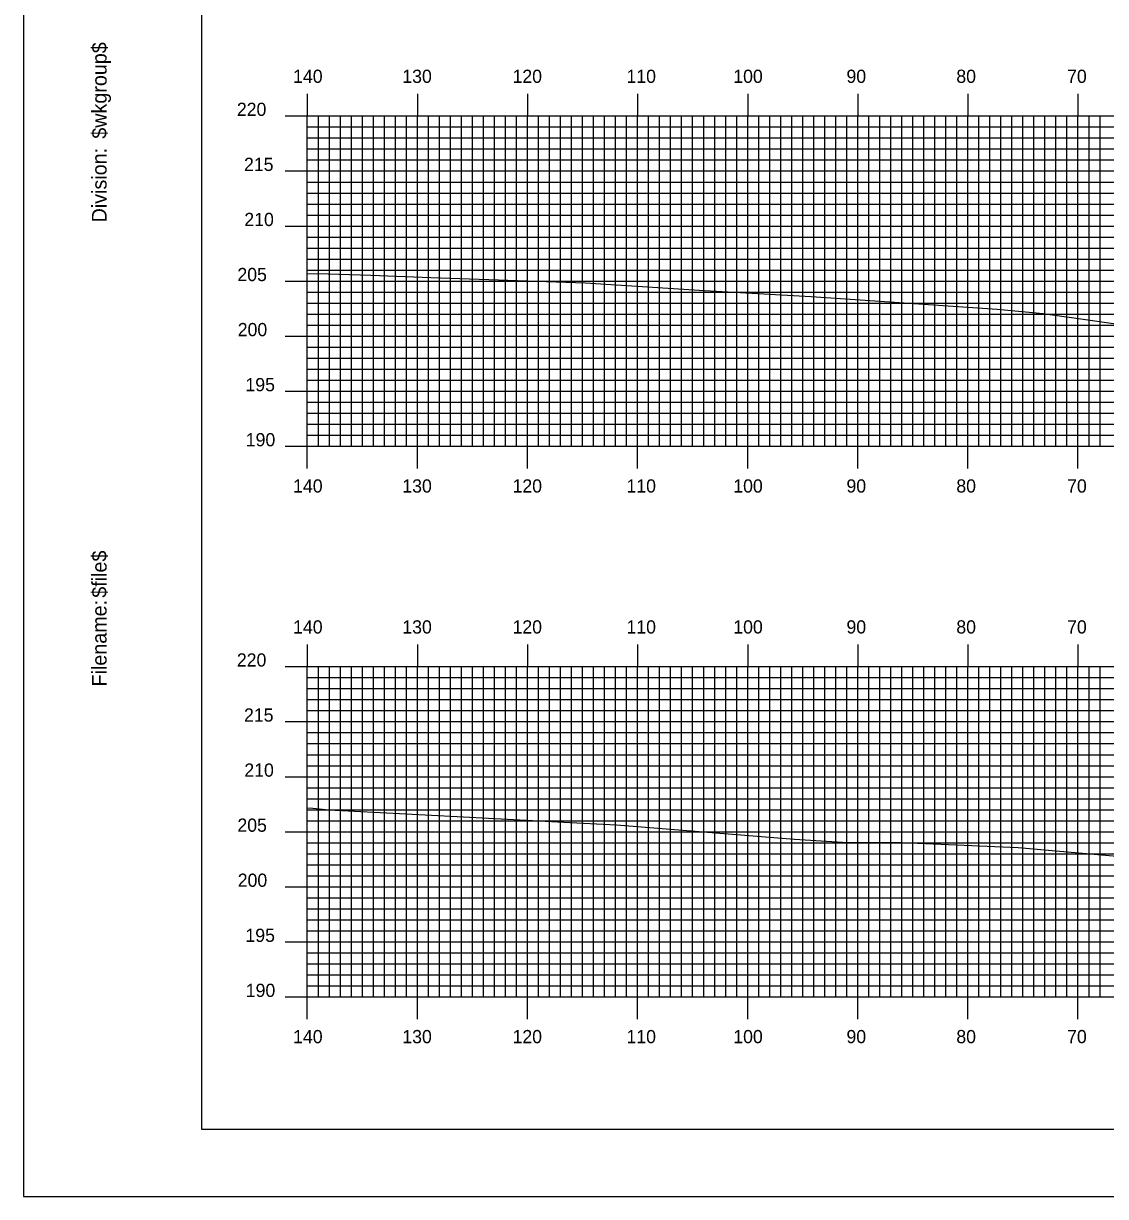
# Model space of a CAD drawing. Extents: x 1806258 to 1806601, y 442591 to 442811.
# Drawn here: x 1806257.9 to 1806356.2, y 442590.5 to 442697.1 of the extents above; entities that cross this region are included whole.
import ezdxf

# ---------------------------------------------------------------- set-up
doc = ezdxf.new("R2010")
doc.units = 0
for name, color, linetype in [('BORDER', 7, 'Continuous'), ('H_V ANNOTATION', 7, 'Continuous'), ('MAJOR', 7, 'Continuous'), ('MINOR', 7, 'Continuous'), ('PLOT BOUNDARY', 7, 'Continuous'), ('S_Roadway_Centerline', 7, 'Continuous')]:
    doc.layers.add(name, color=color, linetype=linetype)

msp = doc.modelspace()

# ---------------------------------------------------------------- linework, layer by layer
at = {"layer": 'BORDER'}
msp.add_lwpolyline([(1806274.13, 442596.67), (1806594.13, 442596.67), (1806594.13, 442806.67), (1806274.13, 442806.67)], close=True, dxfattribs=at)
at = {"layer": 'MAJOR'}
for p, q in [((1806283.73, 442690.67), (1806283.73, 442688.67)), ((1806293.73, 442690.67), (1806293.73, 442688.67)), ((1806303.73, 442690.67), (1806303.73, 442688.67)), ((1806313.73, 442690.67), (1806313.73, 442688.67)), ((1806323.73, 442690.67), (1806323.73, 442688.67)), ((1806333.73, 442690.67), (1806333.73, 442688.67)), ((1806343.73, 442690.67), (1806343.73, 442688.67)), ((1806353.73, 442690.67), (1806353.73, 442688.67)), ((1806281.73, 442688.67), (1806283.73, 442688.67)), ((1806283.73, 442688.67), (1806563.73, 442688.67)), ((1806283.73, 442658.67), (1806283.73, 442688.67)), ((1806283.73, 442658.67), (1806283.73, 442688.67)), ((1806283.73, 442688.67), (1806563.73, 442688.67)), ((1806293.73, 442658.67), (1806293.73, 442688.67)), ((1806303.73, 442658.67), (1806303.73, 442688.67)), ((1806313.73, 442658.67), (1806313.73, 442688.67)), ((1806323.73, 442658.67), (1806323.73, 442688.67)), ((1806333.73, 442658.67), (1806333.73, 442688.67)), ((1806343.73, 442658.67), (1806343.73, 442688.67)), ((1806353.73, 442658.67), (1806353.73, 442688.67)), ((1806281.73, 442683.67), (1806283.73, 442683.67)), ((1806283.73, 442683.67), (1806563.73, 442683.67)), ((1806281.73, 442678.67), (1806283.73, 442678.67)), ((1806283.73, 442678.67), (1806563.73, 442678.67)), ((1806281.73, 442673.67), (1806283.73, 442673.67)), ((1806283.73, 442673.67), (1806563.73, 442673.67)), ((1806281.73, 442668.67), (1806283.73, 442668.67)), ((1806283.73, 442668.67), (1806563.73, 442668.67)), ((1806281.73, 442663.67), (1806283.73, 442663.67)), ((1806283.73, 442663.67), (1806563.73, 442663.67)), ((1806281.73, 442658.67), (1806283.73, 442658.67)), ((1806283.73, 442658.67), (1806563.73, 442658.67)), ((1806283.73, 442658.67), (1806563.73, 442658.67)), ((1806283.73, 442656.66), (1806283.73, 442658.67)), ((1806293.73, 442656.66), (1806293.73, 442658.67)), ((1806303.73, 442656.66), (1806303.73, 442658.67)), ((1806313.73, 442656.66), (1806313.73, 442658.67)), ((1806323.73, 442656.66), (1806323.73, 442658.67)), ((1806333.73, 442656.66), (1806333.73, 442658.67)), ((1806343.73, 442656.66), (1806343.73, 442658.67)), ((1806353.73, 442656.66), (1806353.73, 442658.67)), ((1806283.73, 442640.67), (1806283.73, 442638.67)), ((1806293.73, 442640.67), (1806293.73, 442638.67)), ((1806303.73, 442640.67), (1806303.73, 442638.67)), ((1806313.73, 442640.67), (1806313.73, 442638.67)), ((1806323.73, 442640.67), (1806323.73, 442638.67)), ((1806333.73, 442640.67), (1806333.73, 442638.67)), ((1806343.73, 442640.67), (1806343.73, 442638.67)), ((1806353.73, 442640.67), (1806353.73, 442638.67)), ((1806281.73, 442638.67), (1806283.73, 442638.67)), ((1806283.73, 442638.67), (1806563.73, 442638.67)), ((1806283.73, 442608.67), (1806283.73, 442638.67)), ((1806283.73, 442608.67), (1806283.73, 442638.67)), ((1806283.73, 442638.67), (1806563.73, 442638.67)), ((1806293.73, 442608.67), (1806293.73, 442638.67)), ((1806303.73, 442608.67), (1806303.73, 442638.67)), ((1806313.73, 442608.67), (1806313.73, 442638.67)), ((1806323.73, 442608.67), (1806323.73, 442638.67)), ((1806333.73, 442608.67), (1806333.73, 442638.67)), ((1806343.73, 442608.67), (1806343.73, 442638.67)), ((1806353.73, 442608.67), (1806353.73, 442638.67)), ((1806281.73, 442633.67), (1806283.73, 442633.67)), ((1806283.73, 442633.67), (1806563.73, 442633.67)), ((1806281.73, 442628.67), (1806283.73, 442628.67)), ((1806283.73, 442628.67), (1806563.73, 442628.67)), ((1806281.73, 442623.67), (1806283.73, 442623.67)), ((1806283.73, 442623.67), (1806563.73, 442623.67)), ((1806281.73, 442618.67), (1806283.73, 442618.67)), ((1806283.73, 442618.67), (1806563.73, 442618.67)), ((1806281.73, 442613.67), (1806283.73, 442613.67)), ((1806283.73, 442613.67), (1806563.73, 442613.67)), ((1806281.73, 442608.67), (1806283.73, 442608.67)), ((1806283.73, 442608.67), (1806563.73, 442608.67)), ((1806283.73, 442608.67), (1806563.73, 442608.67)), ((1806283.73, 442606.66), (1806283.73, 442608.67)), ((1806293.73, 442606.66), (1806293.73, 442608.67)), ((1806303.73, 442606.66), (1806303.73, 442608.67)), ((1806313.73, 442606.66), (1806313.73, 442608.67)), ((1806323.73, 442606.66), (1806323.73, 442608.67)), ((1806333.73, 442606.66), (1806333.73, 442608.67)), ((1806343.73, 442606.66), (1806343.73, 442608.67)), ((1806353.73, 442606.66), (1806353.73, 442608.67))]:
    msp.add_line(p, q, dxfattribs=at)
at = {"layer": 'MINOR'}
for p, q in [((1806284.73, 442658.67), (1806284.73, 442688.67)), ((1806285.73, 442658.67), (1806285.73, 442688.67)), ((1806286.73, 442658.67), (1806286.73, 442688.67)), ((1806287.73, 442658.67), (1806287.73, 442688.67)), ((1806288.73, 442658.67), (1806288.73, 442688.67)), ((1806289.73, 442658.67), (1806289.73, 442688.67)), ((1806290.73, 442658.67), (1806290.73, 442688.67)), ((1806291.73, 442658.67), (1806291.73, 442688.67)), ((1806292.73, 442658.67), (1806292.73, 442688.67)), ((1806294.73, 442658.67), (1806294.73, 442688.67)), ((1806295.73, 442658.67), (1806295.73, 442688.67)), ((1806296.73, 442658.67), (1806296.73, 442688.67)), ((1806297.73, 442658.67), (1806297.73, 442688.67)), ((1806298.73, 442658.67), (1806298.73, 442688.67)), ((1806299.73, 442658.67), (1806299.73, 442688.67)), ((1806300.73, 442658.67), (1806300.73, 442688.67)), ((1806301.73, 442658.67), (1806301.73, 442688.67)), ((1806302.73, 442658.67), (1806302.73, 442688.67)), ((1806304.73, 442658.67), (1806304.73, 442688.67)), ((1806305.73, 442658.67), (1806305.73, 442688.67)), ((1806306.73, 442658.67), (1806306.73, 442688.67)), ((1806307.73, 442658.67), (1806307.73, 442688.67)), ((1806308.73, 442658.67), (1806308.73, 442688.67)), ((1806309.73, 442658.67), (1806309.73, 442688.67)), ((1806310.73, 442658.67), (1806310.73, 442688.67)), ((1806311.73, 442658.67), (1806311.73, 442688.67)), ((1806312.73, 442658.67), (1806312.73, 442688.67)), ((1806314.73, 442658.67), (1806314.73, 442688.67)), ((1806315.73, 442658.67), (1806315.73, 442688.67)), ((1806316.73, 442658.67), (1806316.73, 442688.67)), ((1806317.73, 442658.67), (1806317.73, 442688.67)), ((1806318.73, 442658.67), (1806318.73, 442688.67)), ((1806319.73, 442658.67), (1806319.73, 442688.67)), ((1806320.73, 442658.67), (1806320.73, 442688.67)), ((1806321.73, 442658.67), (1806321.73, 442688.67)), ((1806322.73, 442658.67), (1806322.73, 442688.67)), ((1806324.73, 442658.67), (1806324.73, 442688.67)), ((1806325.73, 442658.67), (1806325.73, 442688.67)), ((1806326.73, 442658.67), (1806326.73, 442688.67)), ((1806327.73, 442658.67), (1806327.73, 442688.67)), ((1806328.73, 442658.67), (1806328.73, 442688.67)), ((1806329.73, 442658.67), (1806329.73, 442688.67)), ((1806330.73, 442658.67), (1806330.73, 442688.67)), ((1806331.73, 442658.67), (1806331.73, 442688.67)), ((1806332.73, 442658.67), (1806332.73, 442688.67)), ((1806334.73, 442658.67), (1806334.73, 442688.67)), ((1806335.73, 442658.67), (1806335.73, 442688.67)), ((1806336.73, 442658.67), (1806336.73, 442688.67)), ((1806337.73, 442658.67), (1806337.73, 442688.67)), ((1806338.73, 442658.67), (1806338.73, 442688.67)), ((1806339.73, 442658.67), (1806339.73, 442688.67)), ((1806340.73, 442658.67), (1806340.73, 442688.67)), ((1806341.73, 442658.67), (1806341.73, 442688.67)), ((1806342.73, 442658.67), (1806342.73, 442688.67)), ((1806344.73, 442658.67), (1806344.73, 442688.67)), ((1806345.73, 442658.67), (1806345.73, 442688.67)), ((1806346.73, 442658.67), (1806346.73, 442688.67)), ((1806347.73, 442658.67), (1806347.73, 442688.67)), ((1806348.73, 442658.67), (1806348.73, 442688.67)), ((1806349.73, 442658.67), (1806349.73, 442688.67)), ((1806350.73, 442658.67), (1806350.73, 442688.67)), ((1806351.73, 442658.67), (1806351.73, 442688.67)), ((1806352.73, 442658.67), (1806352.73, 442688.67)), ((1806354.73, 442658.67), (1806354.73, 442688.67)), ((1806355.73, 442658.67), (1806355.73, 442688.67)), ((1806283.73, 442687.67), (1806563.73, 442687.67)), ((1806283.73, 442687.67), (1806285.74, 442687.67)), ((1806283.73, 442686.67), (1806563.73, 442686.67)), ((1806283.73, 442686.67), (1806285.74, 442686.67)), ((1806283.73, 442685.67), (1806563.73, 442685.67)), ((1806283.73, 442685.67), (1806285.74, 442685.67)), ((1806283.73, 442684.67), (1806563.73, 442684.67)), ((1806283.73, 442684.67), (1806285.74, 442684.67)), ((1806283.73, 442682.67), (1806563.73, 442682.67)), ((1806283.73, 442682.67), (1806285.74, 442682.67)), ((1806283.73, 442681.67), (1806563.73, 442681.67)), ((1806283.73, 442681.67), (1806285.74, 442681.67)), ((1806283.73, 442680.67), (1806563.73, 442680.67)), ((1806283.73, 442680.67), (1806285.74, 442680.67)), ((1806283.73, 442679.67), (1806563.73, 442679.67)), ((1806283.73, 442679.67), (1806285.74, 442679.67)), ((1806283.73, 442677.67), (1806563.73, 442677.67)), ((1806283.73, 442677.67), (1806285.74, 442677.67)), ((1806283.73, 442676.67), (1806563.73, 442676.67)), ((1806283.73, 442676.67), (1806285.74, 442676.67)), ((1806283.73, 442675.67), (1806563.73, 442675.67)), ((1806283.73, 442675.67), (1806285.74, 442675.67)), ((1806283.73, 442674.67), (1806563.73, 442674.67)), ((1806283.73, 442674.67), (1806285.74, 442674.67)), ((1806283.73, 442672.67), (1806563.73, 442672.67)), ((1806283.73, 442672.67), (1806285.74, 442672.67)), ((1806283.73, 442671.67), (1806563.73, 442671.67)), ((1806283.73, 442671.67), (1806285.74, 442671.67)), ((1806283.73, 442670.67), (1806563.73, 442670.67)), ((1806283.73, 442670.67), (1806285.74, 442670.67)), ((1806283.73, 442669.67), (1806563.73, 442669.67)), ((1806283.73, 442669.67), (1806285.74, 442669.67)), ((1806283.73, 442667.67), (1806563.73, 442667.67)), ((1806283.73, 442667.67), (1806285.74, 442667.67)), ((1806283.73, 442666.67), (1806563.73, 442666.67)), ((1806283.73, 442666.67), (1806285.74, 442666.67)), ((1806283.73, 442665.67), (1806563.73, 442665.67)), ((1806283.73, 442665.67), (1806285.74, 442665.67)), ((1806283.73, 442664.67), (1806563.73, 442664.67)), ((1806283.73, 442664.67), (1806285.74, 442664.67)), ((1806283.73, 442662.67), (1806563.73, 442662.67)), ((1806283.73, 442662.67), (1806285.74, 442662.67)), ((1806283.73, 442661.67), (1806563.73, 442661.67)), ((1806283.73, 442661.67), (1806285.74, 442661.67)), ((1806283.73, 442660.67), (1806563.73, 442660.67)), ((1806283.73, 442660.67), (1806285.74, 442660.67)), ((1806283.73, 442659.67), (1806563.73, 442659.67)), ((1806283.73, 442659.67), (1806285.74, 442659.67)), ((1806283.73, 442637.67), (1806563.73, 442637.67)), ((1806283.73, 442637.67), (1806285.74, 442637.67)), ((1806284.73, 442608.67), (1806284.73, 442638.67)), ((1806285.73, 442608.67), (1806285.73, 442638.67)), ((1806286.73, 442608.67), (1806286.73, 442638.67)), ((1806287.73, 442608.67), (1806287.73, 442638.67)), ((1806288.73, 442608.67), (1806288.73, 442638.67)), ((1806289.73, 442608.67), (1806289.73, 442638.67)), ((1806290.73, 442608.67), (1806290.73, 442638.67)), ((1806291.73, 442608.67), (1806291.73, 442638.67)), ((1806292.73, 442608.67), (1806292.73, 442638.67)), ((1806294.73, 442608.67), (1806294.73, 442638.67)), ((1806295.73, 442608.67), (1806295.73, 442638.67)), ((1806296.73, 442608.67), (1806296.73, 442638.67)), ((1806297.73, 442608.67), (1806297.73, 442638.67)), ((1806298.73, 442608.67), (1806298.73, 442638.67)), ((1806299.73, 442608.67), (1806299.73, 442638.67)), ((1806300.73, 442608.67), (1806300.73, 442638.67)), ((1806301.73, 442608.67), (1806301.73, 442638.67)), ((1806302.73, 442608.67), (1806302.73, 442638.67)), ((1806304.73, 442608.67), (1806304.73, 442638.67)), ((1806305.73, 442608.67), (1806305.73, 442638.67)), ((1806306.73, 442608.67), (1806306.73, 442638.67)), ((1806307.73, 442608.67), (1806307.73, 442638.67)), ((1806308.73, 442608.67), (1806308.73, 442638.67)), ((1806309.73, 442608.67), (1806309.73, 442638.67)), ((1806310.73, 442608.67), (1806310.73, 442638.67)), ((1806311.73, 442608.67), (1806311.73, 442638.67)), ((1806312.73, 442608.67), (1806312.73, 442638.67)), ((1806314.73, 442608.67), (1806314.73, 442638.67)), ((1806315.73, 442608.67), (1806315.73, 442638.67)), ((1806316.73, 442608.67), (1806316.73, 442638.67)), ((1806317.73, 442608.67), (1806317.73, 442638.67)), ((1806318.73, 442608.67), (1806318.73, 442638.67)), ((1806319.73, 442608.67), (1806319.73, 442638.67)), ((1806320.73, 442608.67), (1806320.73, 442638.67)), ((1806321.73, 442608.67), (1806321.73, 442638.67)), ((1806322.73, 442608.67), (1806322.73, 442638.67)), ((1806324.73, 442608.67), (1806324.73, 442638.67)), ((1806325.73, 442608.67), (1806325.73, 442638.67)), ((1806326.73, 442608.67), (1806326.73, 442638.67)), ((1806327.73, 442608.67), (1806327.73, 442638.67)), ((1806328.73, 442608.67), (1806328.73, 442638.67)), ((1806329.73, 442608.67), (1806329.73, 442638.67)), ((1806330.73, 442608.67), (1806330.73, 442638.67)), ((1806331.73, 442608.67), (1806331.73, 442638.67)), ((1806332.73, 442608.67), (1806332.73, 442638.67)), ((1806334.73, 442608.67), (1806334.73, 442638.67)), ((1806335.73, 442608.67), (1806335.73, 442638.67)), ((1806336.73, 442608.67), (1806336.73, 442638.67)), ((1806337.73, 442608.67), (1806337.73, 442638.67)), ((1806338.73, 442608.67), (1806338.73, 442638.67)), ((1806339.73, 442608.67), (1806339.73, 442638.67)), ((1806340.73, 442608.67), (1806340.73, 442638.67)), ((1806341.73, 442608.67), (1806341.73, 442638.67)), ((1806342.73, 442608.67), (1806342.73, 442638.67)), ((1806344.73, 442608.67), (1806344.73, 442638.67)), ((1806345.73, 442608.67), (1806345.73, 442638.67)), ((1806346.73, 442608.67), (1806346.73, 442638.67)), ((1806347.73, 442608.67), (1806347.73, 442638.67)), ((1806348.73, 442608.67), (1806348.73, 442638.67)), ((1806349.73, 442608.67), (1806349.73, 442638.67)), ((1806350.73, 442608.67), (1806350.73, 442638.67)), ((1806351.73, 442608.67), (1806351.73, 442638.67)), ((1806352.73, 442608.67), (1806352.73, 442638.67)), ((1806354.73, 442608.67), (1806354.73, 442638.67)), ((1806355.73, 442608.67), (1806355.73, 442638.67)), ((1806283.73, 442636.67), (1806563.73, 442636.67)), ((1806283.73, 442636.67), (1806285.74, 442636.67)), ((1806283.73, 442635.67), (1806563.73, 442635.67)), ((1806283.73, 442635.67), (1806285.74, 442635.67)), ((1806283.73, 442634.67), (1806563.73, 442634.67)), ((1806283.73, 442634.67), (1806285.74, 442634.67)), ((1806283.73, 442632.67), (1806563.73, 442632.67)), ((1806283.73, 442632.67), (1806285.74, 442632.67)), ((1806283.73, 442631.67), (1806563.73, 442631.67)), ((1806283.73, 442631.67), (1806285.74, 442631.67)), ((1806283.73, 442630.67), (1806563.73, 442630.67)), ((1806283.73, 442630.67), (1806285.74, 442630.67)), ((1806283.73, 442629.67), (1806563.73, 442629.67)), ((1806283.73, 442629.67), (1806285.74, 442629.67)), ((1806283.73, 442627.67), (1806563.73, 442627.67)), ((1806283.73, 442627.67), (1806285.74, 442627.67)), ((1806283.73, 442626.67), (1806563.73, 442626.67)), ((1806283.73, 442626.67), (1806285.74, 442626.67)), ((1806283.73, 442625.67), (1806563.73, 442625.67)), ((1806283.73, 442625.67), (1806285.74, 442625.67)), ((1806283.73, 442624.67), (1806563.73, 442624.67)), ((1806283.73, 442624.67), (1806285.74, 442624.67)), ((1806283.73, 442622.67), (1806563.73, 442622.67)), ((1806283.73, 442622.67), (1806285.74, 442622.67)), ((1806283.73, 442621.67), (1806563.73, 442621.67)), ((1806283.73, 442621.67), (1806285.74, 442621.67)), ((1806283.73, 442620.67), (1806563.73, 442620.67)), ((1806283.73, 442620.67), (1806285.74, 442620.67)), ((1806283.73, 442619.67), (1806563.73, 442619.67)), ((1806283.73, 442619.67), (1806285.74, 442619.67)), ((1806283.73, 442617.67), (1806563.73, 442617.67)), ((1806283.73, 442617.67), (1806285.74, 442617.67)), ((1806283.73, 442616.67), (1806563.73, 442616.67)), ((1806283.73, 442616.67), (1806285.74, 442616.67)), ((1806283.73, 442615.67), (1806563.73, 442615.67)), ((1806283.73, 442615.67), (1806285.74, 442615.67)), ((1806283.73, 442614.67), (1806563.73, 442614.67)), ((1806283.73, 442614.67), (1806285.74, 442614.67)), ((1806283.73, 442612.67), (1806563.73, 442612.67)), ((1806283.73, 442612.67), (1806285.74, 442612.67)), ((1806283.73, 442611.67), (1806563.73, 442611.67)), ((1806283.73, 442611.67), (1806285.74, 442611.67)), ((1806283.73, 442610.67), (1806563.73, 442610.67)), ((1806283.73, 442610.67), (1806285.74, 442610.67)), ((1806283.73, 442609.67), (1806563.73, 442609.67)), ((1806283.73, 442609.67), (1806285.74, 442609.67))]:
    msp.add_line(p, q, dxfattribs=at)
at = {"layer": 'PLOT BOUNDARY'}
msp.add_lwpolyline([(1806257.95, 442590.55), (1806597.95, 442590.55), (1806597.95, 442810.55), (1806257.95, 442810.55)], close=True, dxfattribs=at)
at = {"layer": 'S_Roadway_Centerline'}
for points in [[(1806283.73, 442674.37), (1806285.61, 442674.32), (1806289.5, 442674.22), (1806294.94, 442674), (1806308.98, 442673.52), (1806319.8, 442672.81), (1806329.5, 442672.27), (1806346.39, 442671.13), (1806350.56, 442670.73), (1806359.54, 442669.46), (1806371.43, 442668.84), (1806371.44, 442668.84), (1806371.45, 442668.84), (1806384.31, 442668.49), (1806403.66, 442667.79), (1806407.19, 442667.64), (1806413.32, 442667.19), (1806424.78, 442666.86), (1806430.48, 442666.82), (1806448.88, 442666.41), (1806452.93, 442666.31), (1806456.31, 442666.14)], [(1806283.73, 442625.83), (1806284.23, 442625.8), (1806285.69, 442625.66), (1806297.34, 442625.07), (1806307.6, 442624.5), (1806311.82, 442624.29), (1806327.98, 442623), (1806332.35, 442622.71), (1806337.77, 442622.68), (1806348.31, 442622.25), (1806362.78, 442620.97), (1806370.38, 442620.74), (1806388.95, 442619.86), (1806390.18, 442619.75), (1806391.27, 442619.71), (1806407.24, 442619.04), (1806413.33, 442618.79), (1806414.32, 442618.74), (1806425.22, 442618.43), (1806441.41, 442617.78), (1806448.11, 442617.46), (1806463.03, 442616.97)]]:
    msp.add_lwpolyline(points, dxfattribs=at)

# ---------------------------------------------------------------- texts
at = {"layer": 'BORDER'}
for s, p in [('$wkgroup$', (1806265.5, 442686.6)), ('Division:', (1806265.5, 442679)), ('$file$', (1806265.5, 442644.92)), ('Filename:', (1806265.5, 442636.86))]:
    msp.add_text(s, height=1.339, rotation=90, dxfattribs=at).set_placement(p)
at = {"layer": 'H_V ANNOTATION'}
for s, p in [('140', (1806282.44, 442691.67)), ('130', (1806292.36, 442691.67)), ('120', (1806302.37, 442691.67)), ('110', (1806312.72, 442691.67)), ('100', (1806322.42, 442691.67)), ('90', (1806332.7, 442691.67)), ('80', (1806342.68, 442691.67)), ('70', (1806352.74, 442691.67)), ('220', (1806277.33, 442688.67)), ('215', (1806277.98, 442683.67)), ('210', (1806278.01, 442678.67)), ('205', (1806277.38, 442673.67)), ('200', (1806277.41, 442668.67)), ('195', (1806278.11, 442663.67)), ('190', (1806278.14, 442658.67)), ('140', (1806282.44, 442654.47)), ('130', (1806292.36, 442654.47)), ('120', (1806302.37, 442654.47)), ('110', (1806312.72, 442654.47)), ('100', (1806322.42, 442654.47)), ('90', (1806332.7, 442654.47)), ('80', (1806342.68, 442654.47)), ('70', (1806352.74, 442654.47)), ('140', (1806282.44, 442641.67)), ('130', (1806292.36, 442641.67)), ('120', (1806302.37, 442641.67)), ('110', (1806312.72, 442641.67)), ('100', (1806322.42, 442641.67)), ('90', (1806332.7, 442641.67)), ('80', (1806342.68, 442641.67)), ('70', (1806352.74, 442641.67)), ('220', (1806277.33, 442638.67)), ('215', (1806277.98, 442633.67)), ('210', (1806278.01, 442628.67)), ('205', (1806277.38, 442623.67)), ('200', (1806277.41, 442618.67)), ('195', (1806278.11, 442613.67)), ('190', (1806278.14, 442608.67)), ('140', (1806282.44, 442604.47)), ('130', (1806292.36, 442604.47)), ('120', (1806302.37, 442604.47)), ('110', (1806312.72, 442604.47)), ('100', (1806322.42, 442604.47)), ('90', (1806332.7, 442604.47)), ('80', (1806342.68, 442604.47)), ('70', (1806352.74, 442604.47))]:
    msp.add_text(s, height=1.2, dxfattribs=at).set_placement(p)
at = {"layer": 'MAJOR'}
for p in [(1806283.72, 442658.67), (1806283.72, 442608.67)]:
    msp.add_text('-', height=0.012, dxfattribs=at).set_placement(p)

doc.saveas('drawing.dxf')
